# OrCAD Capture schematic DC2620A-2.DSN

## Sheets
1 PAGE1: size Custom; note: 7-BIT CURRENT DAC WITH DIGITAL POWER SYSTEM MANAGEMENT
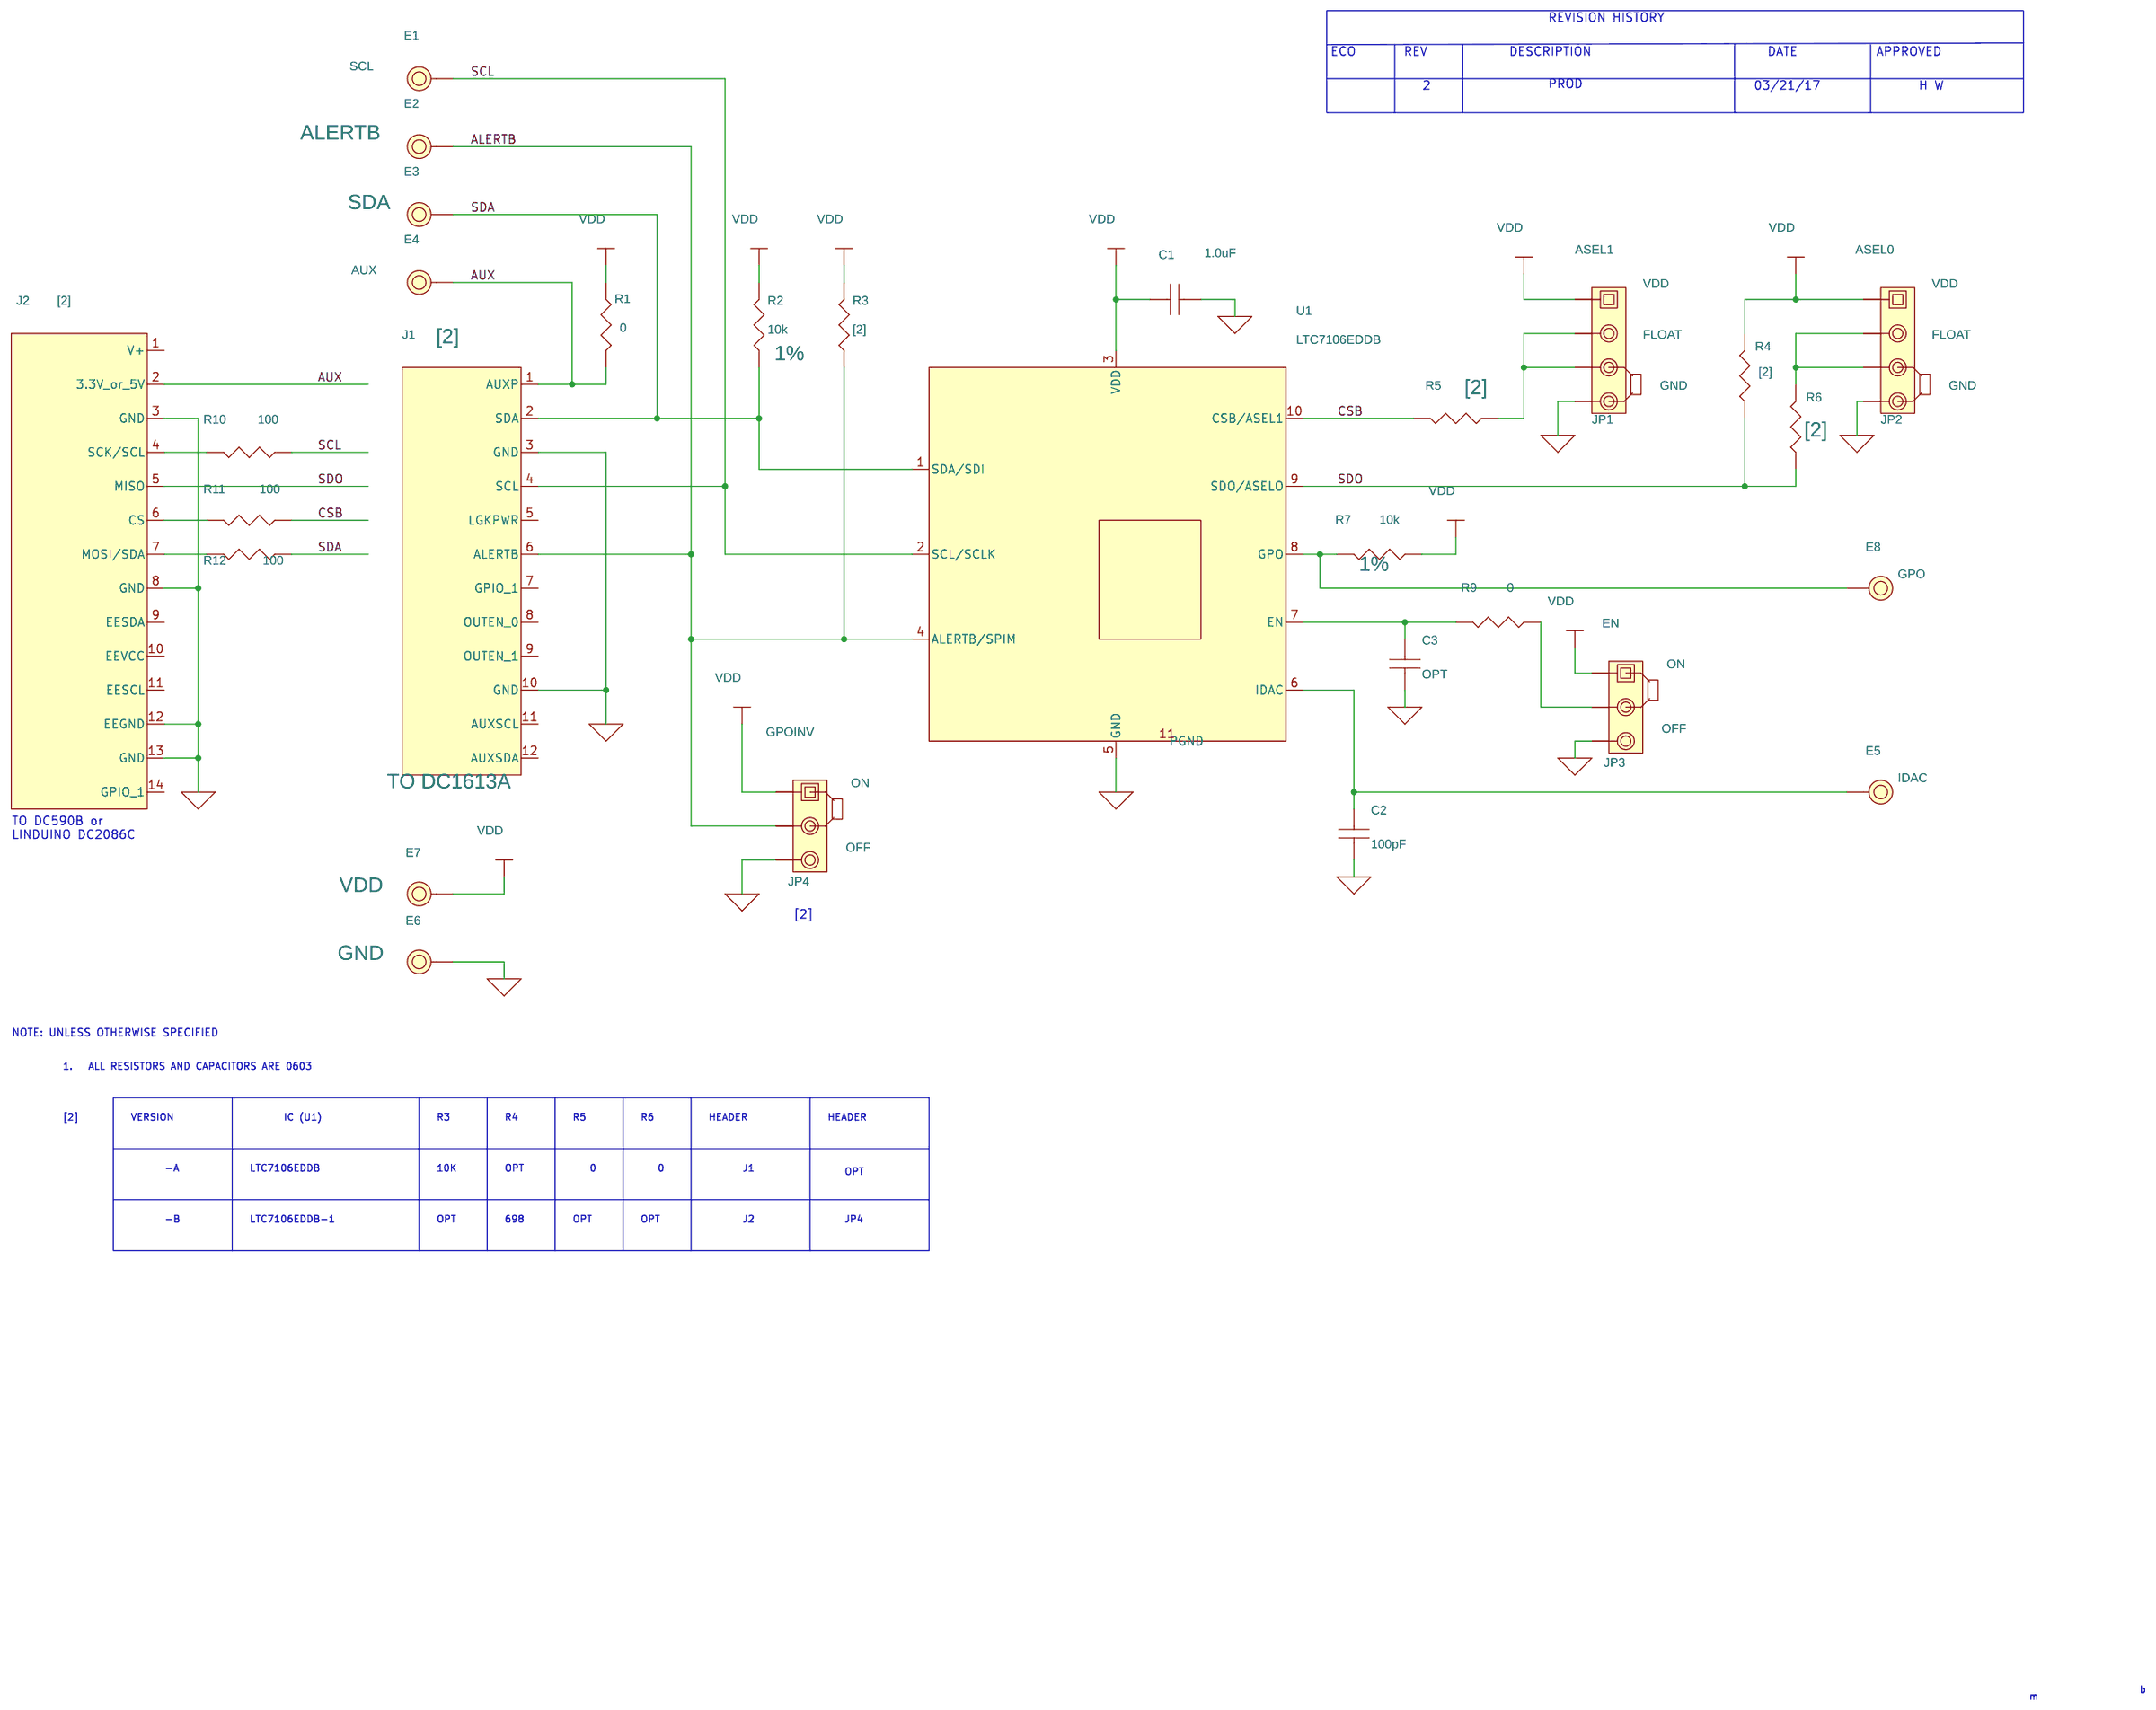
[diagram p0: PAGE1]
2 PAGE2
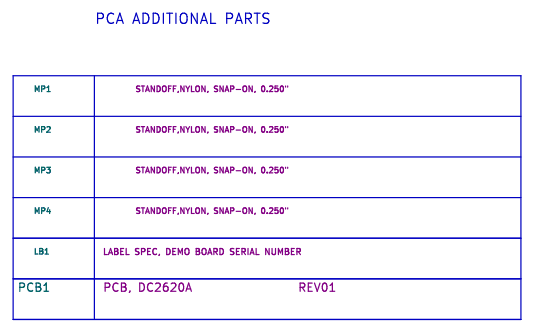
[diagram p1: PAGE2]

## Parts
sheet PAGE1
C1  1.0uF  [CC0603N]
C2  100pF  [CC0603N]
C3  OPT  [CC0603N]
E1  TEST POINT  [MILLMAX2501]
E2  TEST POINT  [MILLMAX2501]
E3  TEST POINT  [MILLMAX2501]
E4  TEST POINT  [MILLMAX2501]
E5  TEST POINT  [MILLMAX2501]
E6  TEST POINT  [MILLMAX2501]
E7  TEST POINT  [MILLMAX2501]
E8  TEST POINT  [MILLMAX2501]
J1  HDR, SHROUDED  [HD2X6-079-MOLEX]
J2  HDR, SHROUDED  [HD2X7-079-MOLEX]
JP1  HDR  [JP4X1/079]
JP2  HDR  [JP4X1/079]
JP3  HDR.  [HD1X3-079]
JP4  HDR.  [HD1X3-079]
R1  0  [CR0603N]
R2  10k  [CR0603N]
R3  [2]  [CR0603N]
R4  OPT  [CR0603N]
R5  OPT  [CR0603N]
R6  OPT  [CR0603N]
R7  10k  [CR0603N]
R9  OPT  [CR0603N]
R10  100  [CR0603N]
R11  100  [CR0603N]
R12  100  [CR0603N]
U1  LTC7106EDDB  [LTC-DDB-10-1722]
XJP1  SHUNT
XJP2  SHUNT
XJP3  SHUNT
XJP4  SHUNT
sheet PAGE2
LB1  LABEL  [895-0154_REV01]
MP1  STANDOFF  [KEYSTONE_8829-8834]
MP2  STANDOFF  [KEYSTONE_8829-8834]
MP3  STANDOFF  [KEYSTONE_8829-8834]
MP4  STANDOFF  [KEYSTONE_8829-8834]
PCB1  PCB, DC2620A

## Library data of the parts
C1 = CAP: CAP., 1.0uF, X5R, 10V, 10%, 0603; CLASS: DISCRETE; Dielectric Type: X5R; Manufacturer: AVX; Manufacturer PN: 0603ZD105KAT2A; PART_NUMBER: TMP-33; Package Size: 0603; Package Type: SMD; Rated Voltage: 10V; Tolerance: 10%
C2 = CAP: CAP., 100pF, X7R, 25V, 5%, 0603; CLASS: DISCRETE; Dielectric Type: X7R; Manufacturer: AVX; Manufacturer PN: 06033C101JAT2A; PART_NUMBER: TMP-22; Package Size: 0603; Package Type: SMD; Rated Voltage: 25V; Tolerance: 5%
C3 = CAP: CAP., OPTION, 0603; CLASS: DISCRETE; PART_NUMBER: 150-3038; Package Size: 0603; Package Type: SMD; UserField01: OPTION
E1 = TESTPOINT_.219_MILL-MAX_2501: TEST POINT,TURRET,0.094",MTG. HOLE; 1st Part Field: SCL; CLASS: IO; Manufacturer: MILL-MAX; Manufacturer PN: 2501-2-00-80-00-00-07-0; PART_NUMBER: 260-0003; Part Number: MIIL-MAX 2501-2-00-80-00-00-07-0
E2 = TESTPOINT_.219_MILL-MAX_2501: TEST POINT,TURRET,0.094",MTG. HOLE; 1st Part Field: ALERTB; CLASS: IO; Manufacturer: MILL-MAX; Manufacturer PN: 2501-2-00-80-00-00-07-0; PART_NUMBER: 260-0003; Part Number: MIIL-MAX 2501-2-00-80-00-00-07-0
E3 = TESTPOINT_.219_MILL-MAX_2501: TEST POINT,TURRET,0.094",MTG. HOLE; 1st Part Field: SDA; CLASS: IO; Manufacturer: MILL-MAX; Manufacturer PN: 2501-2-00-80-00-00-07-0; PART_NUMBER: 260-0003; Part Number: MIIL-MAX 2501-2-00-80-00-00-07-0
E4 = TESTPOINT_.219_MILL-MAX_2501: TEST POINT,TURRET,0.094",MTG. HOLE; 1st Part Field: AUX; CLASS: IO; Manufacturer: MILL-MAX; Manufacturer PN: 2501-2-00-80-00-00-07-0; PART_NUMBER: 260-0003; Part Number: MIIL-MAX 2501-2-00-80-00-00-07-0
E5 = TESTPOINT_.219_MILL-MAX_2501: TEST POINT,TURRET,0.094",MTG. HOLE; 1st Part Field: IDAC; CLASS: IO; Manufacturer: MILL-MAX; Manufacturer PN: 2501-2-00-80-00-00-07-0; PART_NUMBER: 260-0003; Part Number: MIIL-MAX 2501-2-00-80-00-00-07-0
E6 = TESTPOINT_.219_MILL-MAX_2501: TEST POINT,TURRET,0.094",MTG. HOLE; 1st Part Field: GND; CLASS: IO; Manufacturer: MILL-MAX; Manufacturer PN: 2501-2-00-80-00-00-07-0; PART_NUMBER: 260-0003; Part Number: MIIL-MAX 2501-2-00-80-00-00-07-0
E7 = TESTPOINT_.219_MILL-MAX_2501: TEST POINT,TURRET,0.094",MTG. HOLE; 1st Part Field: VDD; CLASS: IO; Manufacturer: MILL-MAX; Manufacturer PN: 2501-2-00-80-00-00-07-0; PART_NUMBER: 260-0003; Part Number: MIIL-MAX 2501-2-00-80-00-00-07-0
E8 = TESTPOINT_.219_MILL-MAX_2501: TEST POINT,TURRET,0.094",MTG. HOLE; 1st Part Field: GPO; CLASS: IO; Manufacturer: MILL-MAX; Manufacturer PN: 2501-2-00-80-00-00-07-0; PART_NUMBER: 260-0003; Part Number: MIIL-MAX 2501-2-00-80-00-00-07-0
J1 = CONN_7._FCI_12_POS_2MM: CONN.,HDR, SHROUDED,2x6,2mm,THT, VERT; 1st Part Field: [2]; 2nd Part Field: TO DC1613A; CLASS: IO; Manufacturer: FCI; Manufacturer PN: 98414-G06-12ULF; PART_NUMBER: 250-0433
J2 = CONN_MOLEX_14_POS_2MM_ALT1: CONN.,HDR, SHROUDED,2x7,2mm,THT, VERT; 1st Part Field: [2]; 2nd Part Field: TO DC590B or Linduino DC2026C; CLASS: IO; Manufacturer: MOLEX; Manufacturer PN: 87831-1420; PART_NUMBER: TMP-1775
JP1 = HDR1X4_ALT1: CONN.,HDR,MALE,1x4,2mm,THT, STR; 10th Part Field: VDD; 11th Part Field: FLOAT; 12th Part Field: GND; 9th Part Field: ASEL1; CLASS: IO; FPLIST: JP4X1/079,HD1X4-079; Manufacturer: WURTH ELEKTRONIK; Manufacturer PN: 62000411121; PART_NUMBER: 250-0563
JP2 = HDR1X4_ALT1: CONN.,HDR,MALE,1x4,2mm,THT, STR; 10th Part Field: VDD; 11th Part Field: FLOAT; 12th Part Field: GND; 9th Part Field: ASEL0; CLASS: IO; FPLIST: JP4X1/079,HD1X4-079; Manufacturer: WURTH ELEKTRONIK; Manufacturer PN: 62000411121; PART_NUMBER: 250-0563
JP3 = HDR1X3_ALT1: CONN.,HDR.,MALE,1x3,2mm,THT, STR; 11th Part Field: OFF; 12th Part Field: EN; 9th Part Field: ON; CLASS: IO; Manufacturer: SULLINS CONNECTOR SOLUTIONS; Manufacturer PN: NRPN031PAEN-RC; PART_NUMBER: 250-0418
JP4 = HDR1X3_ALT1: CONN.,HDR.,MALE,1x3,2mm,THT, STR; 11th Part Field: OFF; 12th Part Field: GPOINV; 9th Part Field: ON; CLASS: IO; Manufacturer: SULLINS CONNECTOR SOLUTIONS; Manufacturer PN: NRPN031PAEN-RC; PART_NUMBER: 250-0418
R1 = RES: RES.,0 OHM,1/10W,0603; CLASS: DISCRETE; Manufacturer: VISHAY; Manufacturer PN: CRCW06030000Z0EA; PART_NUMBER: 100-0009; Package Size: 0603; Part Number: VISHAY CRCW06030000Z0EA; Rated Power: 1/10W
R2 R3 = RES: RES.,10k OHMS,1%,1/10W,0603; CLASS: DISCRETE; Manufacturer: KOA SPEER; Manufacturer PN: RK73H1JTTD1002F; PART_NUMBER: 100-2012; Package Size: 0603; Part Number: RK73H1JTTD1002F; Rated Power: 1/10W; Temperature Coefficient: +/-100ppm/C; Tolerance: 1%
R4-R6 = RES: RES., OPTION, 0603; 1st Part Field: [2]; CLASS: DISCRETE; FPLIST: CR0603N,CR0603L,CR0603M; PART_NUMBER: 100-2374; Package Size: 0603; Part Number: OPTION
R7 = RES: RES.,10k OHMS,1%,1/10W,0603; CLASS: DISCRETE; Manufacturer: KOA SPEER; Manufacturer PN: RK73H1JTTD1002F; PART_NUMBER: 100-2012; Package Size: 0603; Rated Power: 1/10W; Temperature Coefficient: +/-100ppm/C; Tolerance: 1%
R9 = RES: RES., 0 OHM,1/10W / OPTION, 0603; 1st Part Field: 0; CLASS: DISCRETE; FPLIST: CR0603N,CR0603L,CR0603M; Manufacturer PN: CRCW06030000Z0EA / option; PART_NUMBER: 100-0009 / 100-2374; Package Size: 0603; Part Number: VISHAY CRCW06030000Z0EA / OPTION
R10-R12 = RES: RES.,100 OHMS,1%,1/10W,0603; CLASS: DISCRETE; FPLIST: CR0603N,CR0603L,CR0603M; Manufacturer: NIC; Manufacturer PN: NRC06F1000TRF; PART_NUMBER: 100-2586; Package Size: 0603; Part Number: OPTION; Rated Power: 1/10W; Temperature Coefficient: 100ppm; Tolerance: 1%
U1 = LTC7106-DDB-X_2: IC, DAC 7-BIT CURRENT DAC; CLASS: IC; Manufacturer: LINEAR TECHNOLOGY; PART_NUMBER: TMP-1784; Package Type: 10-DFN, 3X3mm
XJP1-XJP4 = SHUNT_2MM: CONN.,SHUNT,FEMALE,2 POS,2mm; CLASS: IO; Manufacturer: Wurth Elektronik; Manufacturer PN: 60800213421; PART_NUMBER: 250-0485; Part Number: Wurth Elektronik 60800213421
LB1 = BLANK_LABEL: LABEL SPEC, DEMO BOARD SERIAL NUMBER; Manufacturer: BRADY; Manufacturer PN: THT-96-717-10; PART_NUMBER: 895-0154
MP1-MP4 = BLANK_MECHANICAL_PART: STANDOFF,NYLON, SNAP-ON, 0.250"; CLASS: MECHANICAL PART; Manufacturer: KEYSTONE; Manufacturer PN: 8831; PART_NUMBER: 763-0006
PCB1 = BLANK_PCB_PART: BOM Notes: REV01; CLASS: DISCRETE; Manufacturer: LINEAR TECHNOLOGY; Manufacturer PN: 600-DC2620A; PART_NUMBER: TMP-1849

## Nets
PGND: C1.2 C2.2 C3.2 E6.1 J1.3(GND) J1.10(GND) J2.3(GND) J2.8(GND) J2.12(EEGND) J2.13(GND) JP1.4 JP2.4 JP3.3 JP4.3 U1.5(GND) U1.11(PGND)
VDD: C1.1 E7.1 JP1.1 JP2.1 JP3.1 JP4.1 R1.2 R2.2 R3.2 R4.1 R7.1 U1.3(VDD)
ALERTB: E2.1 J1.6(ALERTB) JP4.2 R3.1 U1.4(ALERTB/SPIM)
AUX: E4.1 J1.1(AUXP) J2.2(3.3V_or_5V) R1.1
CSB: R5.2 R11.1 U1.10(CSB/ASEL1)
SCL: E1.1 J1.4(SCL) R10.1 U1.2(SCL/SCLK)
SDA: E3.1 J1.2(SDA) R2.1 R12.1 U1.1(SDA/SDI)
SDO: J2.5(MISO) R4.2 R6.2 U1.9(SDO/ASELO)
N16450086: JP1.2 JP1.3 R5.1
N16450721: JP2.2 JP2.3 R6.1
N16451300: E8.1 R7.2 U1.8(GPO)
N16451753: C2.1 E5.1 U1.6(IDAC)
N16495747: JP3.2 R9.1
N16495751: C3.1 R9.2 U1.7(EN)
N16503391: J2.4(SCK/SCL) R10.2
N16503415: J2.6(CS) R11.2
N16503419: J2.7(MOSI/SDA) R12.2

Not connected (* = marked no-connect by the designer): J1 5(LGKPWR) 7(GPIO_1) 8(OUTEN_0) 9(OUTEN_1) 11(AUXSCL) 12(AUXSDA); J2 1(V+) 9(EESDA) 10(EEVCC) 11(EESCL) 14(GPIO_1)

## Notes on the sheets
sheet 1
- REVISION HISTORY
- ECO
- REV
- DESCRIPTION
- DATE
- APPROVED
- 2
- PROD
- 03/21/17
- H W
- TO DC590B or
  LINDUINO DC2086C
- [2]
- NOTE: UNLESS OTHERWISE SPECIFIED
- 1.   ALL RESISTORS AND CAPACITORS ARE 0603
- [2]
- VERSION
- IC (U1)
- R3
- R4
- R5
- R6
- HEADER
- HEADER
- -A
- LTC7106EDDB
- 10K
- OPT
- 0
- 0
- J1
- OPT
- -B
- LTC7106EDDB-1
- OPT
- 698
- OPT
- OPT
- J2
- JP4
- m
- b
sheet 2
- PCA ADDITIONAL PARTS
